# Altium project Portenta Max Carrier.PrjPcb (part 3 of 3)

## Sheet LORA.SchDoc: LORA
size A4; Author: Arturo Guadalupi; CompanyName: Arduino srl; DocumentNumber: ABX00043; Revision: V3.10; SheetNumber: 6; SheetTotal: 14; RevAuthor: S. Navaretti
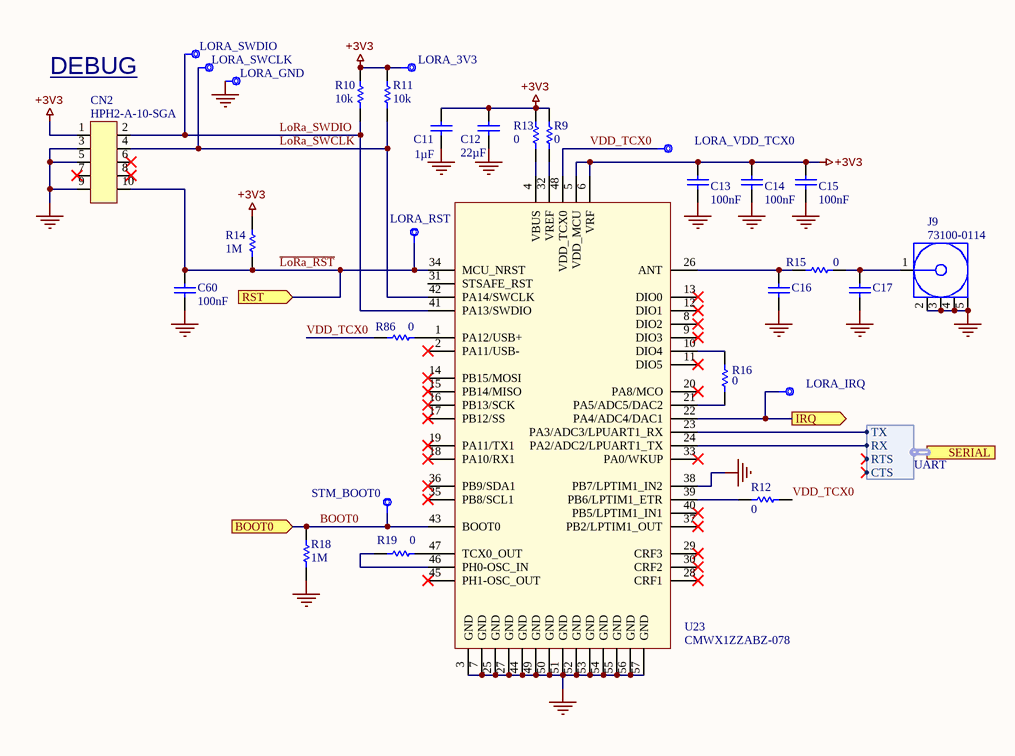
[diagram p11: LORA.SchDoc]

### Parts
C11  value 1µF  [CAP-0402]  (hidden comment: C0402C105K8PACTU)
C12  value 22µF  [CAP-0805]  (hidden comment: CL21A226MAQNNNE)
C13  value 100nF  [CAP-0402]  (hidden comment: C0402C104K4RACTU)
C14  value 100nF  [CAP-0402]  (hidden comment: C0402C104K4RACTU)
C15  value 100nF  [CAP-0402]  (hidden comment: C0402C104K4RACTU)
C16  C0402C104K4RACTU  [CAP-0402]  (value not drawn)
C17  C0402C104K4RACTU  [CAP-0402]  (value not drawn)
C60  value 100nF  [CAP-0402]  (hidden comment: C0402C104K4RACTU)
CN2  HPH2-A-10-SGA  [PINHEAD_2X05_127]
J9  73100-0114  [MOLX-731000114_V]
LORA_3V3  CMP-018-0005-A.3  [TP-1.00MM]  (value not drawn)  (no BOM)
LORA_GND  CMP-018-0005-A.3  [TP-1.00MM]  (value not drawn)  (no BOM)
LORA_IRQ  CMP-018-0005-A.3  [TP-1.00MM]  (value not drawn)  (no BOM)
LORA_RST  CMP-018-0005-A.3  [TP-1.00MM]  (value not drawn)  (no BOM)
LORA_SWCLK  CMP-018-0005-A.3  [TP-1.00MM]  (value not drawn)  (no BOM)
LORA_SWDIO  CMP-018-0005-A.3  [TP-1.00MM]  (value not drawn)  (no BOM)
LORA_VDD_TCX0  CMP-018-0005-A.3  [TP-1.00MM]  (value not drawn)  (no BOM)
R9  value 0  [RES-0402]  (hidden comment: CRCW04020000Z0EDC)
R10  value 10k  [RES-0402]  (hidden comment: CRCW040210K0FKED)
R11  value 10k  [RES-0402]  (hidden comment: CRCW040210K0FKED)
R12  value 0  [RES-0402]  (hidden comment: CRCW04020000Z0EDC)
R13  value 0  [RES-0402]  (hidden comment: CRCW04020000Z0EDC)
R14  value 1M  [RES-0402]  (hidden comment: CRCW04021M00FKED)
R15  value 0  [RES-0402]  (hidden comment: CRCW04020000Z0EDC)
R16  value 0  [RES-0402]  (hidden comment: CRCW04020000Z0EDC)
R18  value 1M  [RES-0402]  (hidden comment: CRCW04021M00FKED)
R19  value 0  [RES-0402]  (hidden comment: CRCW04020000Z0EDC)
R86  value 0  [RES-0402]  (hidden comment: CRCW04020000Z0EDC)
STM_BOOT0  CMP-018-0005-A.3  [TP-1.00MM]  (value not drawn)  (no BOM)
U23  CMWX1ZZABZ-078  [CMWX1ZZABZ]

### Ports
BOOT0 (in), IRQ (out), RST (in), SERIAL (harness UART)

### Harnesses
UART: CTS, RTS, RX, TX

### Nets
+3V3: C11.2 C12.2 C13.2 C14.2 C15.2 CN2.1 LORA_3V3.X R9.2 R10.2 R11.2 R13.2 R14.2 U23.5(VDD_MCU) U23.6(VRF)
GND: C11.1 C12.1 C13.1 C14.1 C15.1 C16.1 C17.1 C60.1 CN2.3 CN2.5 CN2.9 J9.2 J9.3 J9.4 J9.5 LORA_GND.X R18.2 U23.3(GND) U23.7(GND) U23.25(GND) U23.27(GND) U23.38(PB7/LPTIM1_IN2) U23.44(GND) U23.49(GND) U23.50(GND) U23.51(GND) U23.52(GND) U23.53(GND) U23.54(GND) U23.55(GND) U23.56(GND) U23.57(GND)
~{LoRa_RST}: C60.2 CN2.10 LORA_RST.X R14.1 U23.34(MCU_NRST) ; port RST  [project net GPIO.3]
BOOT0: R18.1 STM_BOOT0.X U23.43(BOOT0) ; port BOOT0  [project net LORA_BOOT0]
LORA_IRQ: LORA_IRQ.X U23.22(PA4/ADC4/DAC1) ; port IRQ
LoRa_SWCLK: CN2.4 LORA_SWCLK.X R11.1 U23.42(PA14/SWCLK)  [project net LoRa_SWCLK_6]
LoRa_SWDIO: CN2.2 LORA_SWDIO.X R10.1 U23.41(PA13/SWDIO)  [project net LoRa_SWDIO_6]
SERIAL3.RX: U23.24(PA2/ADC2/LPUART1_TX) ; port SERIAL.RX
SERIAL3.TX: U23.23(PA3/ADC3/LPUART1_RX) ; port SERIAL.TX
VDD_TCX0: LORA_VDD_TCX0.X R12.1 R86.2 U23.48(VDD_TCX0)  [project net VDD_TCX0_6]
NetC16_2: C16.2 R15.1 U23.26(ANT)
NetC17_2: C17.2 J9.1 R15.2
NetR9_1: R9.1 U23.32(VREF)
NetR12_2: R12.2 U23.39(PB6/LPTIM1_ETR)
NetR13_1: R13.1 U23.4(VBUS)
NetR16_1: R16.1 U23.10(DIO4)
NetR16_2: R16.2 U23.21(PA5/ADC5/DAC2)
NetR19_1: R19.1 U23.47(TCX0_OUT)
NetR19_2: R19.2 U23.46(PH0-OSC_IN)
NetR86_1: R86.1 U23.1(PA12/USB+)

Not connected (* = marked no-connect by the designer): CN2 6* 7* 8*; U23 2(PA11/USB-)* 8(DIO2)* 9(DIO3)* 11(DIO5)* 12(DIO1)* 13(DIO0)* 14(PB15/MOSI)* 15(PB14/MISO)* 16(PB13/SCK)* 17(PB12/SS)* 18(PA10/RX1)* 19(PA11/TX1)* 20(PA8/MCO)* 28(CRF1)* 29(CRF3)* 30(CRF2)* 31(STSAFE_RST) 33(PA0/WKUP)* 35(PB8/SCL1)* 36(PB9/SDA1)* 37(PB2/LPTIM1_OUT)* 40(PB5/LPTIM1_IN1)* 45(PH1-OSC_OUT)*

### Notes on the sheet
- DEBUG

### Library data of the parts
C11 = C0017-A.9: CAP CHIP 0402 1uF 10V X5R 10%; Manufacturer: KEMET; Code Arduino: 0133
C12 = C0111-A.2: CAP CHIP 0805 22uF 25V X5R 20%; Manufacturer: Samsung Electro-Mechanics; Code Arduino: C0111
C13-C17 C60 = C0012-A.9: CAP CHIP 0402 100nF 16V X7R 10%; Manufacturer: KEMET; Code Arduino: 0132
CN2 = J0068-A.5: CONN CONN STRIP THD 1,27 M/2/D 10v AuF H6,3 JTAG; Manufacturer: Adam Tech; Code Arduino: 0171
J9 = J0084-A.2: CONN PCB JACK RECEPTACLE SMA RA 50 OHM; Manufacturer: Molex; Impedance: 50R; Dielectric Material: PTFE; Body Plating: Gold; Connector Type: SMA,Socket; Frequency: 12Hz; Max Frequency: 18GHz; Code Arduino: J0084; Body Material: Brass; Voltage Rating: 500V
LORA_3V3 LORA_GND LORA_IRQ LORA_RST LORA_SWCLK LORA_SWDIO LORA_VDD_TCX0 STM_BOOT0 = UT0013-A.2: Test point 1.00mm
R9 R12 R13 R15 R16 R19 R86 = R0000-A.5: RES CHIP 0402 0R 1/16W; Manufacturer: Vishay; Power: 63mW; Tolerance: J; Code Arduino: 0039
R10 R11 = R0003-A.5: RES CHIP 0402 10K 1% 1/16W; Manufacturer: Vishay; Code Arduino: 0136; Power: 63mW
R14 R18 = R0058-A.5: RES CHIP 0402 1M 1% 1/16W; Manufacturer: Vishay; Code Arduino: 0139; Power: 63mW
U23 = M0000-A.4: MODULE LoRa; Manufacturer: Murata; Code Arduino: A5491

## Sheet DEBUGGER.SchDoc: DEBUGGER
size A3; Author: Arturo Guadalupi; CompanyName: Arduino srl; DocumentNumber: ABX00043; Revision: V3.10; SheetNumber: 3; SheetTotal: 14; RevAuthor: S. Navaretti
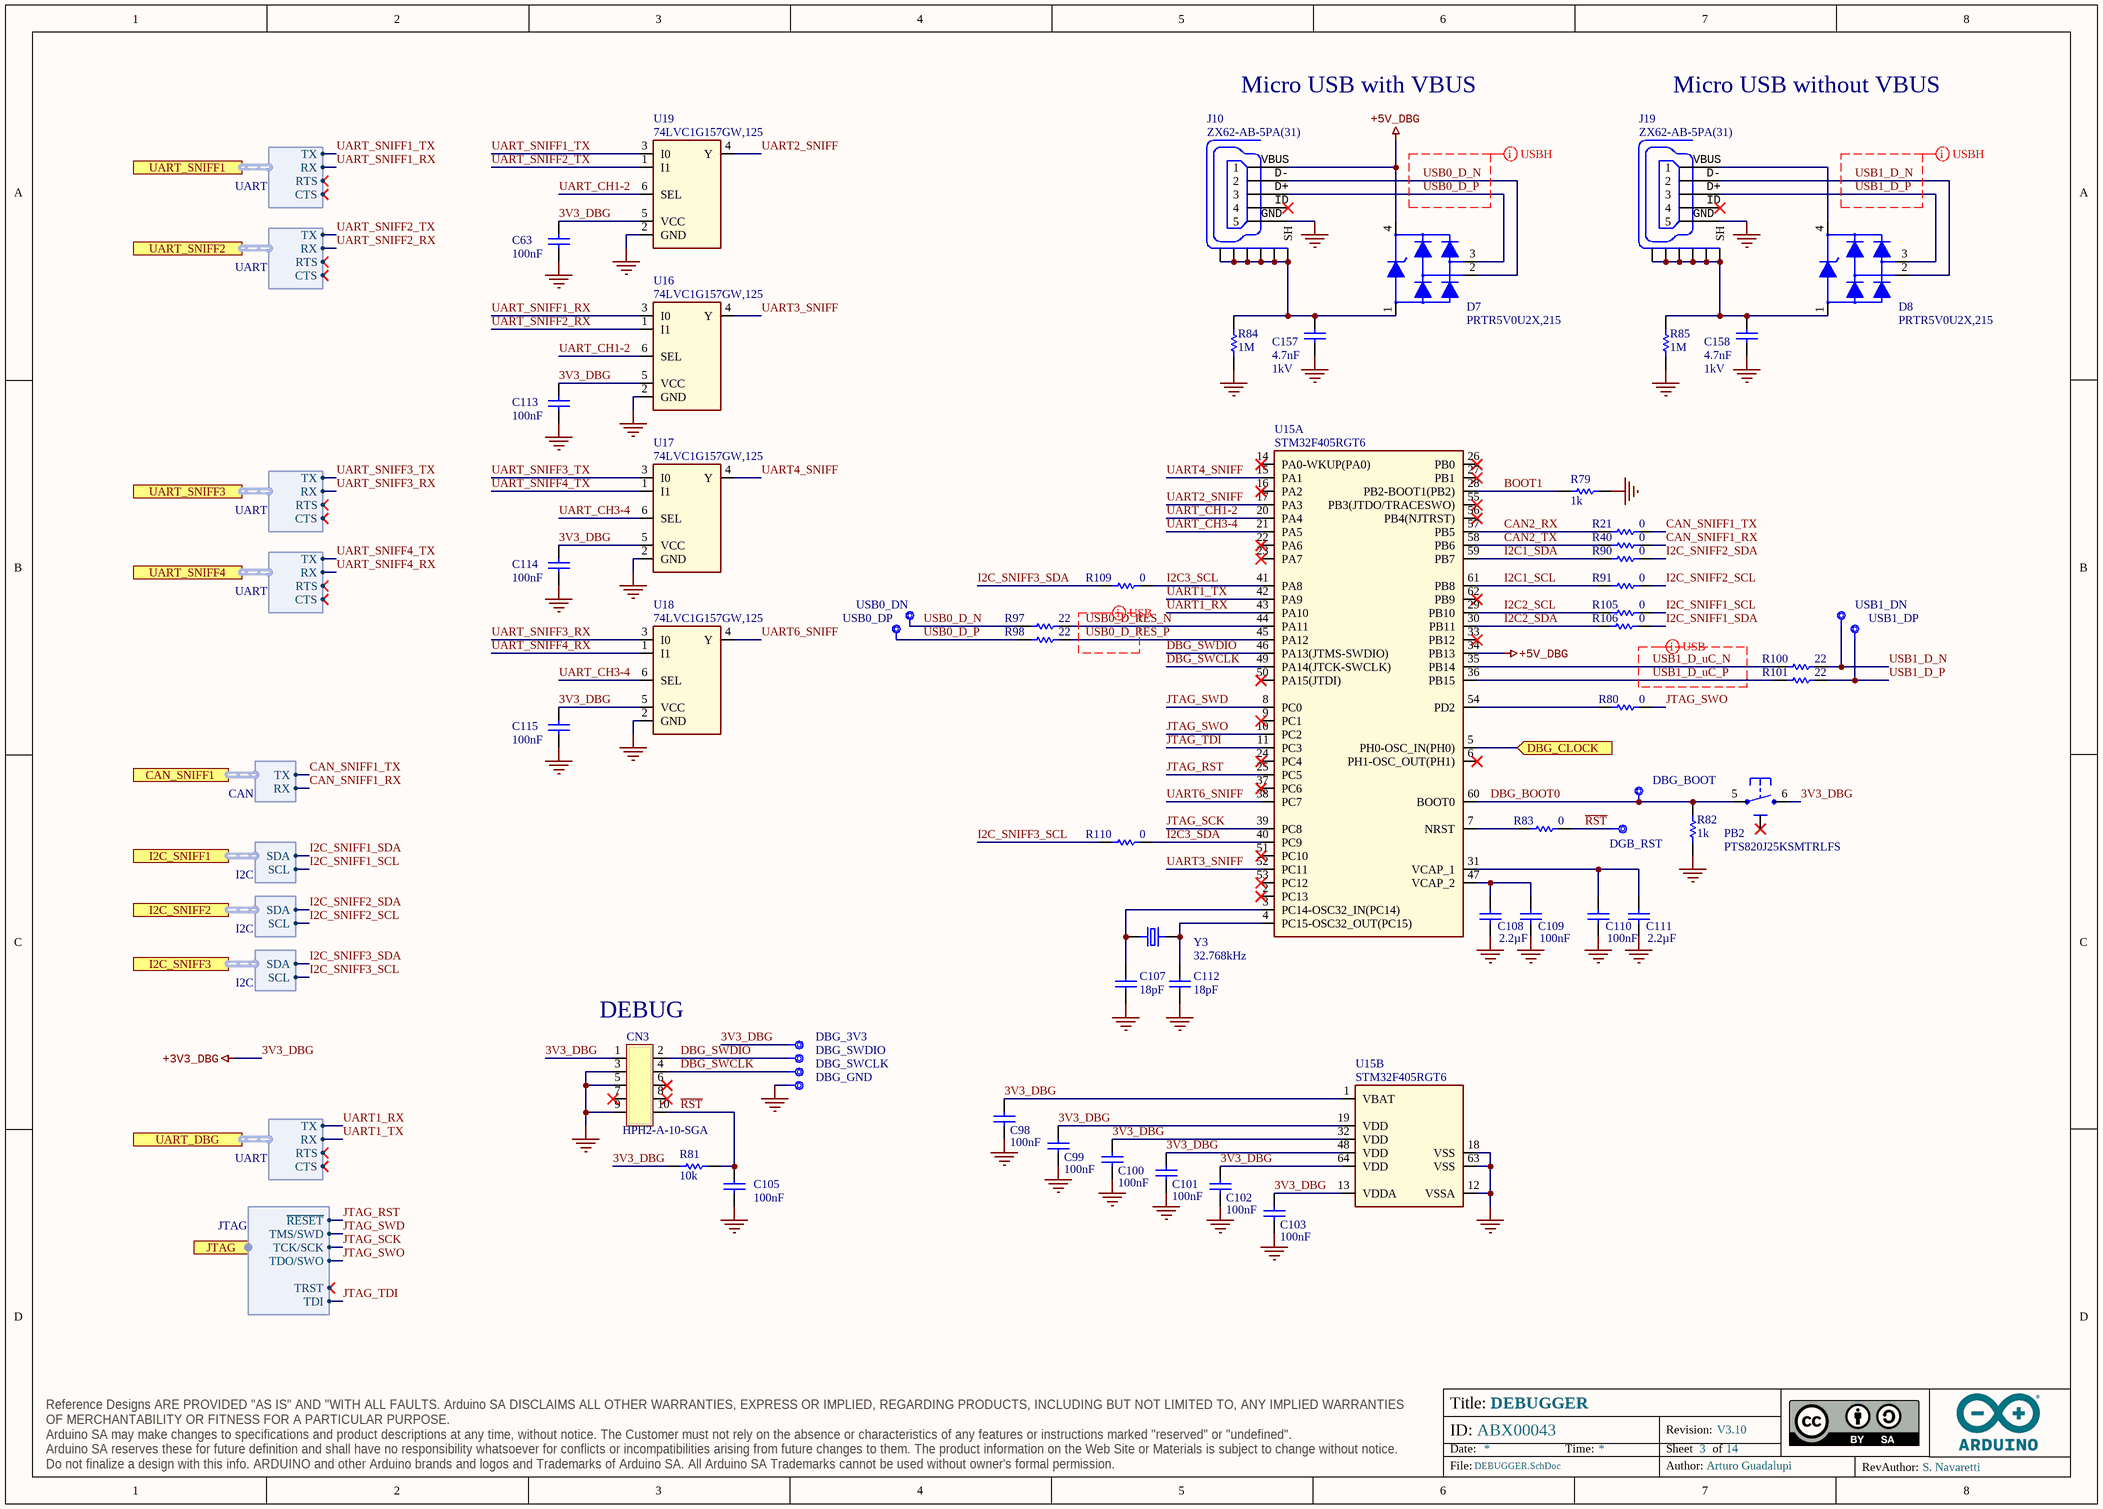
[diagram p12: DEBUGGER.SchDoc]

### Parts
C63  value 100nF  [CAP-0402]  (hidden comment: C0402C104K4RACTU)
C98  value 100nF  [CAP-0402]  (hidden comment: C0402C104K4RACTU)
C99  value 100nF  [CAP-0402]  (hidden comment: C0402C104K4RACTU)
C100  value 100nF  [CAP-0402]  (hidden comment: C0402C104K4RACTU)
C101  value 100nF  [CAP-0402]  (hidden comment: C0402C104K4RACTU)
C102  value 100nF  [CAP-0402]  (hidden comment: C0402C104K4RACTU)
C103  value 100nF  [CAP-0402]  (hidden comment: C0402C104K4RACTU)
C105  value 100nF  [CAP-0402]  (hidden comment: C0402C104K4RACTU)
C107  value 18pF  [CAP-0402]  (hidden comment: C0402C180J5GACTU)
C108  value 2.2µF  [CAP-0402]  (hidden comment: GRM155R60J225KE95D)
C109  value 100nF  [CAP-0402]  (hidden comment: C0402C104K4RACTU)
C110  value 100nF  [CAP-0402]  (hidden comment: C0402C104K4RACTU)
C111  value 2.2µF  [CAP-0402]  (hidden comment: GRM155R60J225KE95D)
C112  value 18pF  [CAP-0402]  (hidden comment: C0402C180J5GACTU)
C113  value 100nF  [CAP-0402]  (hidden comment: C0402C104K4RACTU)
C114  value 100nF  [CAP-0402]  (hidden comment: C0402C104K4RACTU)
C115  value 100nF  [CAP-0402]  (hidden comment: C0402C104K4RACTU)
C157  value 4.7nF  Voltage: 1kV  [CAP-0805]  (hidden comment: C0805C472KDRACTU)
C158  value 4.7nF  Voltage: 1kV  [CAP-0805]  (hidden comment: C0805C472KDRACTU)
CN3  HPH2-A-10-SGA  [PINHEAD_2X05_127]
D7  PRTR5V0U2X,215  [SOT190P230X110-4N]
D8  PRTR5V0U2X,215  [SOT190P230X110-4N]
DBG_3V3  CMP-018-0005-A.3  [TP-1.00MM]  (value not drawn)  (no BOM)
DBG_BOOT  CMP-018-0005-A.3  [TP-1.00MM]  (value not drawn)  (no BOM)
DBG_GND  CMP-018-0005-A.3  [TP-1.00MM]  (value not drawn)  (no BOM)
DBG_SWCLK  CMP-018-0005-A.3  [TP-1.00MM]  (value not drawn)  (no BOM)
DBG_SWDIO  CMP-018-0005-A.3  [TP-1.00MM]  (value not drawn)  (no BOM)
DGB_RST  CMP-018-0005-A.3  [TP-1.00MM]  (value not drawn)  (no BOM)
J10  ZX62-AB-5PA(31)  [ZX62-AB-5PA]
J19  ZX62-AB-5PA(31)  [ZX62-AB-5PA]
PB2  PTS820J25KSMTRLFS  [C&K_PTS820_NO_HOLES-1]
R21  value 0  [RES-0402]  (hidden comment: CRCW04020000Z0EDC)
R40  value 0  [RES-0402]  (hidden comment: CRCW04020000Z0EDC)
R79  value 1k  [RES-0402]  (hidden comment: CRCW04021K00FKEDC)
R80  value 0  [RES-0402]  (hidden comment: CRCW04020000Z0EDC)
R81  value 10k  [RES-0402]  (hidden comment: CRCW040210K0FKED)
R82  value 1k  [RES-0402]  (hidden comment: CRCW04021K00FKEDC)
R83  value 0  [RES-0402]  (hidden comment: CRCW04020000Z0EDC)
R84  value 1M  [RES-0402]  (hidden comment: CRCW04021M00FKED)
R85  value 1M  [RES-0402]  (hidden comment: CRCW04021M00FKED)
R90  value 0  [RES-0402]  (hidden comment: CRCW04020000Z0EDC)
R91  value 0  [RES-0402]  (hidden comment: CRCW04020000Z0EDC)
R97  value 22  [RES-0402]  (hidden comment: RC0402FR-0722RL)
R98  value 22  [RES-0402]  (hidden comment: RC0402FR-0722RL)
R100  value 22  [RES-0402]  (hidden comment: RC0402FR-0722RL)
R101  value 22  [RES-0402]  (hidden comment: RC0402FR-0722RL)
R105  value 0  [RES-0402]  (hidden comment: CRCW04020000Z0EDC)
R106  value 0  [RES-0402]  (hidden comment: CRCW04020000Z0EDC)
R109  value 0  [RES-0402]  (hidden comment: CRCW04020000Z0EDC)
R110  value 0  [RES-0402]  (hidden comment: CRCW04020000Z0EDC)
U15  STM32F405RGT6  [STM-LQFP64_M]  (parts A,B of 2)
U16  74LVC1G157GW,125  [TSOP95P280X110-6N]
U17  74LVC1G157GW,125  [TSOP95P280X110-6N]
U18  74LVC1G157GW,125  [TSOP95P280X110-6N]
U19  74LVC1G157GW,125  [TSOP95P280X110-6N]
USB0_DN  CMP-018-0005-A.3  [TP-1.00MM]  (value not drawn)  (no BOM)
USB0_DP  CMP-018-0005-A.3  [TP-1.00MM]  (value not drawn)  (no BOM)
USB1_DN  CMP-018-0005-A.3  [TP-1.00MM]  (value not drawn)  (no BOM)
USB1_DP  CMP-018-0005-A.3  [TP-1.00MM]  (value not drawn)  (no BOM)
Y3  Frequency: 32.768kHz  [ABS07]  (hidden comment: CM315D32768DZFT)

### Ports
CAN_SNIFF1 (harness CAN), DBG_CLOCK (in), I2C_SNIFF1 (harness I2C), I2C_SNIFF2 (harness I2C), I2C_SNIFF3 (harness I2C), JTAG (harness JTAG), UART_DBG (harness UART), UART_SNIFF1 (harness UART), UART_SNIFF2 (harness UART), UART_SNIFF3 (harness UART), UART_SNIFF4 (harness UART)

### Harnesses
UART: RX, TX, RTS, CTS
I2C: SCL, SDA
CAN: RX, TX
JTAG: ~{RESET}, TCK/SCK, TDI, TDO/SWO, TMS/SWD, TRST

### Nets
+3V3_DBG: C63.1 C98.2 C99.2 C100.2 C101.2 C102.2 C103.2 C113.1 C114.1 C115.1 CN3.1 DBG_3V3.X PB2.6 R81.2 U15.1(VBAT) U15.13(VDDA) U15.19(VDD) U15.32(VDD) U15.48(VDD) U15.64(VDD) U16.5(VCC) U17.5(VCC) U18.5(VCC) U19.5(VCC)  [also labelled 3V3_DBG]
+5V_DBG: D7.4 J10.1 U15.34(PB13)
GND: C63.2 C98.1 C99.1 C100.1 C101.1 C102.1 C103.1 C105.1 C107.2 C108.1 C109.1 C110.1 C111.1 C112.2 C113.2 C114.2 C115.2 C157.1 C158.1 CN3.3 CN3.5 CN3.9 DBG_GND.X J10.5 J19.5 R79.1 R82.1 R84.1 R85.1 U15.12(VSSA) U15.18(VSS) U15.63(VSS) U16.2(GND) U17.2(GND) U18.2(GND) U19.2(GND)
~{RST}: C105.2 CN3.10 DGB_RST.X R81.1 R83.2  [project net ~{RST}_3]
BOOT1: R79.2 U15.28(PB2-BOOT1(PB2))  [project net BOOT1_3]
CAN2_RX: R21.1 U15.57(PB5)  [project net CAN2_RX_3]
CAN2_TX: R40.1 U15.58(PB6)  [project net CAN2_TX_3]
CAN_SNIFF1_RX: R40.2 ; port CAN_SNIFF1.RX  [project net CAN1.RX]
CAN_SNIFF1_TX: R21.2 ; port CAN_SNIFF1.TX  [project net CAN1.TX]
DBG_BOOT0: DBG_BOOT.X PB2.5 R82.2 U15.60(BOOT0)  [project net DBG_BOOT0_3]
DBG_SWCLK: CN3.4 DBG_SWCLK.X U15.49(PA14(JTCK-SWCLK))  [project net DBG_SWCLK_3]
DBG_SWDIO: CN3.2 DBG_SWDIO.X U15.46(PA13(JTMS-SWDIO))  [project net DBG_SWDIO_3]
I2C1_SCL: R91.1 U15.61(PB8)  [project net I2C1_SCL_3]
I2C1_SDA: R90.1 U15.59(PB7)  [project net I2C1_SDA_3]
I2C2_SCL: R105.1 U15.29(PB10)  [project net I2C2_SCL_3]
I2C2_SDA: R106.1 U15.30(PB11)  [project net I2C2_SDA_3]
I2C3_SCL: R109.2 U15.41(PA8)  [project net I2C3_SCL_3]
I2C3_SDA: R110.2 U15.40(PC9)  [project net I2C3_SDA_3]
I2C_SNIFF1_SCL: R105.2 ; port I2C_SNIFF1.SCL  [project net I2C0.SCL]
I2C_SNIFF1_SDA: R106.2 ; port I2C_SNIFF1.SDA  [project net I2C0.SDA]
I2C_SNIFF2_SCL: R91.2 ; port I2C_SNIFF2.SCL  [project net I2C1.SCL]
I2C_SNIFF2_SDA: R90.2 ; port I2C_SNIFF2.SDA  [project net I2C1.SDA]
I2C_SNIFF3_SCL: R110.1 ; port I2C_SNIFF3.SCL  [project net I2C2.SCL]
I2C_SNIFF3_SDA: R109.1 ; port I2C_SNIFF3.SDA  [project net I2C2.SDA]
JTAG_RST: U15.25(PC5) ; port JTAG.~{RESET}  [project net JTAG.~{RESET}]
JTAG_SCK: U15.39(PC8) ; port JTAG.TCK/SCK  [project net JTAG.TCK/SCK]
JTAG_SWD: U15.8(PC0) ; port JTAG.TMS/SWD  [project net JTAG.TMS/SWD]
JTAG_SWO: R80.2 U15.10(PC2) ; port JTAG.TDO/SWO  [project net JTAG.TDO/SWO]
JTAG_TDI: U15.11(PC3) ; port JTAG.TDI  [project net JTAG.TDI]
UART1_RX: U15.43(PA10) ; port UART_DBG.TX  [project net SERIAL2.TX]
UART1_TX: U15.42(PA9) ; port UART_DBG.RX  [project net SERIAL2.RX]
UART2_SNIFF: U15.17(PA3) U19.4(Y)  [project net UART2_SNIFF_3]
UART3_SNIFF: U15.52(PC11) U16.4(Y)  [project net UART3_SNIFF_3]
UART4_SNIFF: U15.15(PA1) U17.4(Y)  [project net UART4_SNIFF_3]
UART6_SNIFF: U15.38(PC7) U18.4(Y)  [project net UART6_SNIFF_3]
UART_CH1-2: U15.20(PA4) U16.6(SEL) U19.6(SEL)  [project net UART_CH1-2_3]
UART_CH3-4: U15.21(PA5) U17.6(SEL) U18.6(SEL)  [project net UART_CH3-4_3]
UART_SNIFF1_RX: U16.3(I0) ; port UART_SNIFF1.RX  [project net SERIAL0.RX]
UART_SNIFF1_TX: U19.3(I0) ; port UART_SNIFF1.TX  [project net SERIAL0.TX]
UART_SNIFF2_RX: U16.1(I1) ; port UART_SNIFF2.RX  [project net SERIAL1.RX]
UART_SNIFF2_TX: U19.1(I1) ; port UART_SNIFF2.TX  [project net SERIAL1.TX]
UART_SNIFF3_RX: U18.3(I0) ; port UART_SNIFF3.RX  [project net SERIAL3.RX]
UART_SNIFF3_TX: U17.3(I0) ; port UART_SNIFF3.TX  [project net SERIAL3.TX]
UART_SNIFF4_RX: U18.1(I1) ; port UART_SNIFF4.RX
UART_SNIFF4_TX: U17.1(I1) ; port UART_SNIFF4.TX
USB0_D_N: D7.2 J10.2 R97.1 USB0_DN.X  [project net USB0_D_N_3]
USB0_D_P: D7.3 J10.3 R98.1 USB0_DP.X  [project net USB0_D_P_3]
USB0_D_RES_N: R97.2 U15.44(PA11)  [project net USB0_D_RES_N_3]
USB0_D_RES_P: R98.2 U15.45(PA12)  [project net USB0_D_RES_P_3]
USB1_D_N: D8.2 J19.2 R100.2 USB1_DN.X  [project net USB1_D_N_3]
USB1_D_P: D8.3 J19.3 R101.2 USB1_DP.X  [project net USB1_D_P_3]
USB1_D_uC_N: R100.1 U15.35(PB14)  [project net USB1_D_uC_N_3]
USB1_D_uC_P: R101.1 U15.36(PB15)  [project net USB1_D_uC_P_3]
Net12MHz_CLK_X: U15.5(PH0-OSC_IN(PH0)) ; port DBG_CLOCK
NetC107_1: C107.1 U15.3(PC14-OSC32_IN(PC14)) Y3.2
NetC108_2: C108.2 C109.2 U15.47(VCAP_2)
NetC110_2: C110.2 C111.2 U15.31(VCAP_1)
NetC112_1: C112.1 U15.4(PC15-OSC32_OUT(PC15)) Y3.1
NetC157_2: C157.2 D7.1 J10.M1(SH) J10.M2(SH) J10.M3(SH) J10.M4(SH) J10.M5(SH) J10.M6(SH) R84.2
NetC158_2: C158.2 D8.1 J19.M1(SH) J19.M2(SH) J19.M3(SH) J19.M4(SH) J19.M5(SH) J19.M6(SH) R85.2
NetD8_4: D8.4 J19.1
NetR80_1: R80.1 U15.54(PD2)
NetR83_1: R83.1 U15.7(NRST)

Not connected (* = marked no-connect by the designer): CN3 6* 7* 8*; J10 4*; J19 4*; PB2 PAD*; U15 2(PC13)* 6(PH1-OSC_OUT(PH1))* 9(PC1)* 14(PA0-WKUP(PA0))* 16(PA2)* 22(PA6)* 23(PA7)* 24(PC4)* 26(PB0)* 27(PB1)* 33(PB12)* 37(PC6)* 50(PA15(JTDI))* 51(PC10)* 53(PC12)* 55(PB3(JTDO/TRACESWO))* 56(PB4(NJTRST))* 62(PB9)*

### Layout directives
differential pair; differential pair class USB: USB0_D_N, USB0_D_P, USB0_D_RES_N, USB0_D_RES_P, USB1_D_N, USB1_D_P, USB1_D_uC_N, USB1_D_uC_P

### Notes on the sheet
- Micro USB with VBUS
- Micro USB without VBUS
- (near CN3) DEBUG

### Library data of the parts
C63 C98-C103 C105 C109 C110 C113-C115 = C0012-A.9: as C13-C17 on sheet LORA
C107 C112 = C0026-A.11: CAP CHIP 0402 18pF C0G 50V 5%; Manufacturer: KEMET; Code Arduino: 2320
C108 C111 = C0031-A.9: CAP CHIP 0402 2.2uF 6.3V X5R 10%; Manufacturer: Murata; Code Arduino: A5529
C157 C158 = C0059-A.9: CAP CHIP 0805 4.7nF 1000V X7R 10%; Manufacturer: KEMET; Code Arduino: 0689
CN3 = J0068-A.5: as CN2 on sheet LORA
D7 D8 = D0025-A.3: TVS ARRAY 4LIN.8kV 1pF SOT143B; Manufacturer: Nexperia; Device Type: ESD protection; Code Arduino: 2209
DBG_3V3 DBG_BOOT DBG_GND DBG_SWCLK DBG_SWDIO DGB_RST USB0_DN USB0_DP USB1_DN USB1_DP = UT0013-A.2: Test point 1.00mm
J10 J19 = J0039-A.3: CONN USB MICRO F/90^ SMD TipoAB 5x1; Manufacturer: Hirose; Code Arduino: 2219
PB2 = B0006-A.6: PUSHBUTTON SMD PTS820 NO HOLES; Manufacturer: C&K; Mechanical Life: 100000Cycles; Code Arduino: A5506; Actuator Type: Standard
R21 R40 R80 R83 R90 R91 R105 R106 R109 R110 = R0000-A.5: RES CHIP 0402 0R 1/16W; Manufacturer: Vishay; Code Arduino: 0039; Power: 63mW; Tolerance: J
R79 R82 = R0007-A.5: RES CHIP 0402 1K 1% 1/16W; Manufacturer: Vishay; Code Arduino: 0140; Power: 63mW
R81 = R0003-A.5: as R10 on sheet LORA
R84 R85 = R0058-A.5: as R14 on sheet LORA
R97 R98 R100 R101 = R0009-A.5: RES CHIP 0402 22R 1% 1/16W; Manufacturer: Yageo; Power: 63mW; Code Arduino: 0468
U15 = U0118-A.4: MCU 32-bit STM32F ARM Cortex M4F RISC 1024KB Flash 2.5V/3.3V 64-Pin LQFP Tray; Manufacturer: ST Microelectronics; Interface: I2C,SPI,USB,CAN,IrDA,UART,USART,LIN,I2S; Min Supply Voltage: 1.8V; Number of Timers/Counters: 14; Data Bus Width: 32b; Number of SPI Channels: 3; Number of Programmable I/O: 51; Watchdog Timer: Yes; Oscillator Type: Internal; Number of ADC Channels: 16; Peripherals: Brown-out Detect/Reset,POR,PWM,WDT,DMA,LCD,I2C; RAM Size: 196KB; Number of UART Channels: 2; Max Frequency: 168MHz; Code Arduino: U0118; Max Supply Voltage: 3.6V
U16-U19 = U0119-A.4: IC SINGLE 2-INPUT MUX 6TSSOP; Manufacturer: Nexperia; Max Supply Voltage: 5.5V; Min Supply Voltage: 1.65V; Code Arduino: U0119
Y3 = X0003-A.4: CRYSTAL 32.768kHz 20ppm 12.5pF SMD 1.6x0.9mm; Manufacturer: Citizen FineDevice; Code Arduino: 0213; Series Resistance: 70kR; Frequency Stability: 0.12%

## Sheet ETH_CONNECTOR.SchDoc: ETHERNET
size A4; Author: Arturo Guadalupi; CompanyName: Arduino srl; DocumentNumber: ABX00043; Revision: V3.10; SheetNumber: 14; SheetTotal: 14; RevAuthor: S. Navaretti
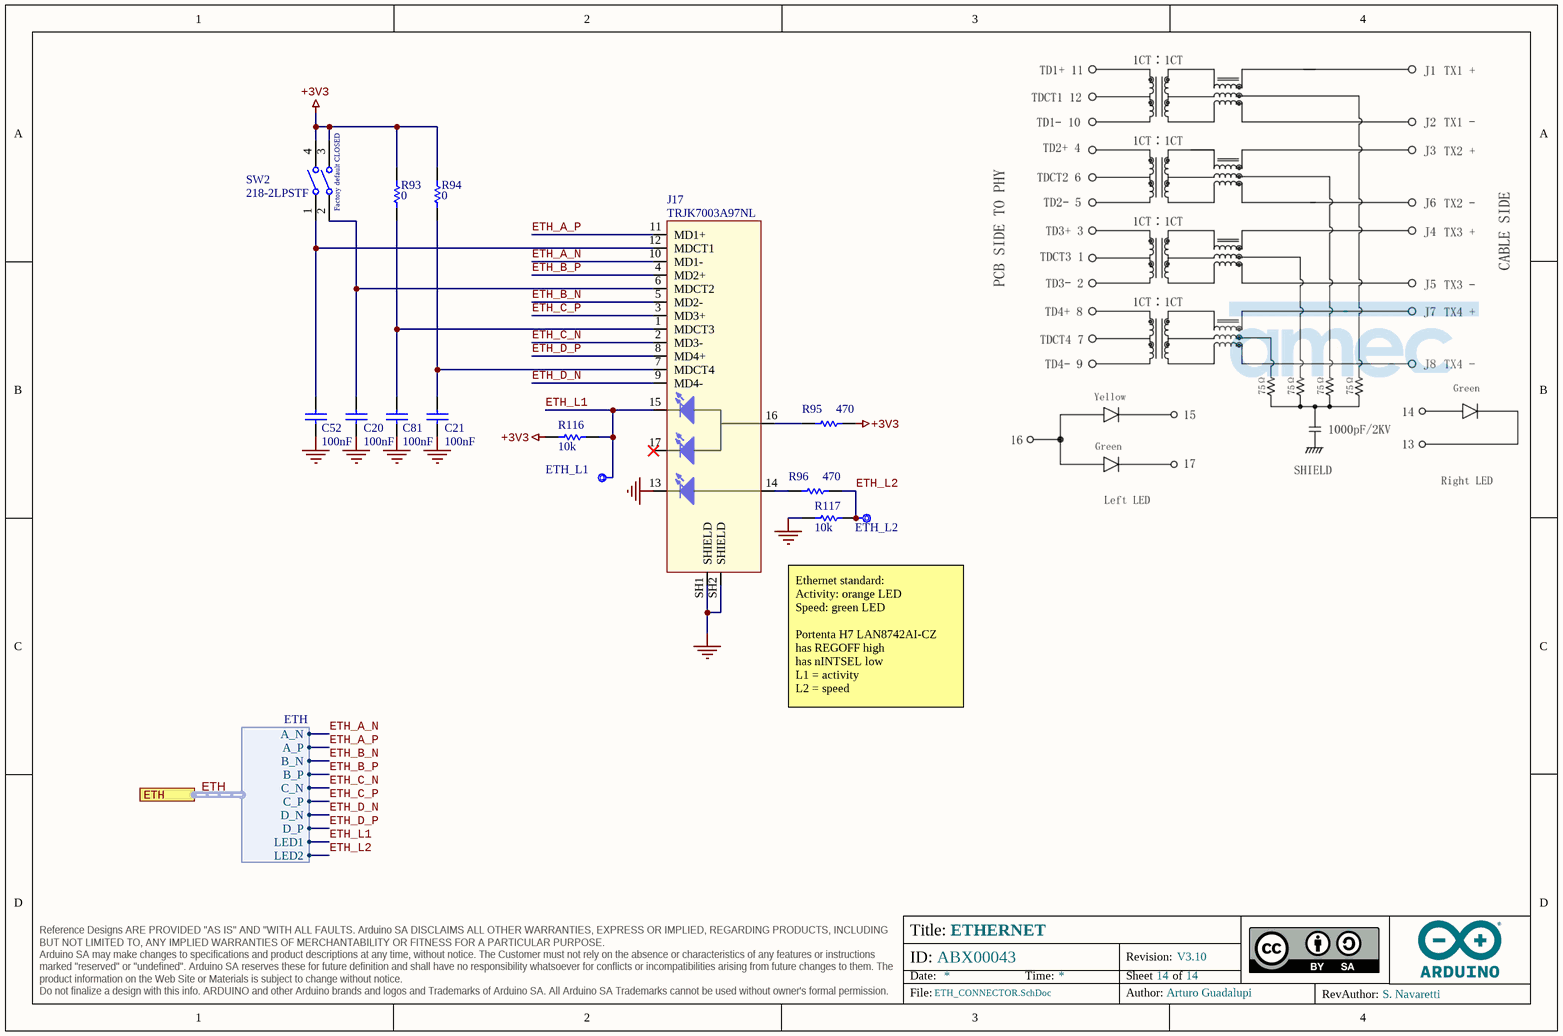
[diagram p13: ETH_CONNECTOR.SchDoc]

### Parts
C20  value 100nF  [CAP-0402]  (hidden comment: C0402C104K4RACTU)
C21  value 100nF  [CAP-0402]  (hidden comment: C0402C104K4RACTU)
C52  value 100nF  [CAP-0402]  (hidden comment: C0402C104K4RACTU)
C81  value 100nF  [CAP-0402]  (hidden comment: C0402C104K4RACTU)
ETH_L1  CMP-018-0005-A.3  [TP-1.00MM]  (value not drawn)  (no BOM)
ETH_L2  CMP-018-0005-A.3  [TP-1.00MM]  (value not drawn)  (no BOM)
J17  TRJK7003A97NL  [TRJK0071AWNL -Footprint-2]
R93  value 0  [RES-0402]  (hidden comment: CRCW04020000Z0EDC)
R94  value 0  [RES-0402]  (hidden comment: CRCW04020000Z0EDC)
R95  value 470  [RES-0402]  (hidden comment: CRCW0402470RJNED)
R96  value 470  [RES-0402]  (hidden comment: CRCW0402470RJNED)
R116  value 10k  [RES-0402]  (hidden comment: CRCW040210K0FKED)
R117  value 10k  [RES-0402]  (hidden comment: CRCW040210K0FKED)
SW2  218-2LPSTF  [CTS-218-2LPST_V]

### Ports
ETH (harness ETH)

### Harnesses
ETH: A_N, A_P, B_N, B_P, C_N, C_P, D_N, D_P, LED1, LED2

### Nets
+3V3: R93.2 R94.2 R95.2 R116.2 SW2.3 SW2.4
GND: C20.2 C21.2 C52.2 C81.2 J17.13 J17.SH1(SHIELD) J17.SH2(SHIELD) R117.2
ETH_A_N: J17.10(MD1-) ; port ETH.A_N  [project net ETH.A_N]
ETH_A_P: J17.11(MD1+) ; port ETH.A_P  [project net ETH.A_P]
ETH_B_N: J17.5(MD2-) ; port ETH.B_N  [project net ETH.B_N]
ETH_B_P: J17.4(MD2+) ; port ETH.B_P  [project net ETH.B_P]
ETH_C_N: J17.2(MD3-) ; port ETH.C_N  [project net ETH.C_N]
ETH_C_P: J17.3(MD3+) ; port ETH.C_P  [project net ETH.C_P]
ETH_D_N: J17.9(MD4-) ; port ETH.D_N  [project net ETH.D_N]
ETH_D_P: J17.8(MD4+) ; port ETH.D_P  [project net ETH.D_P]
ETH_L1: ETH_L1.X J17.15 R116.1 ; port ETH.LED1  [project net ETH.LED1]
ETH_L2: ETH_L2.X R96.2 R117.1 ; port ETH.LED2  [project net ETH.LED2]
NetC20_1: C20.1 J17.6(MDCT2) SW2.2
NetC21_1: C21.1 J17.7(MDCT4) R94.1
NetC52_1: C52.1 J17.12(MDCT1) SW2.1
NetC81_1: C81.1 J17.1(MDCT3) R93.1
NetJ17_14: J17.14 R96.1
NetJ17_16: J17.16 R95.1

Not connected (* = marked no-connect by the designer): J17 17*

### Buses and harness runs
harness ETH = port ETH

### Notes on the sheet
- (near J17) Ethernet standard:
  Activity: orange LED
  Speed: green LED
  Portenta H7 LAN8742AI-CZ
  has REGOFF high
  has nINTSEL low
  L1 = activity
  L2 = speed

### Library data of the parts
C20 C21 C52 C81 = C0012-A.9: as C13-C17 on sheet LORA
ETH_L1 ETH_L2 = UT0013-A.2: Test point 1.00mm
J17 = J0027-A.4: CONN ETHERNET 1GIGABIT; Manufacturer: TRXCOM; Code Arduino: A5565
R93 R94 = R0000-A.5: as R21 on sheet DEBUGGER
R95 R96 = R0055-A.6: RES CHIP 0402 470R 5% 1/16W; Manufacturer: Vishay; Power: 63mW; Code Arduino: R0055; Tolerance: 1%
R116 R117 = R0003-A.5: as R10 on sheet LORA
SW2 = S0016-A.2: DIP SWITCH SPST LATCHED SMD 0.025A, 24VDC, NORMALLY ON; Manufacturer: CTS Corporation; Part Number: 218-2LPSTR; Number of Positions: 2; Actuator Type: Slide (Standard); Washable: Yes; Pitch: 0.05inch; Electrical Life: 1000Cycles; Current Rating: 25mA; Code Arduino: S0016; Voltage Rating (DC): 24V; Contact Resistance: 100mR

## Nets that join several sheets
+1V8: POWER (1V8.X C87.2 U12.5), AUDIO (9 pins)
+3V3: TOP (8 pins), POWER (8 pins), FIELDBUS (10 pins), HDConn_FEMALE (6 pins), AUDIO (9 pins), SD_CONNECTOR (J11.4), CELL_MODEM (10 pins), USB_HUB (8 pins), CAMERA_CONNECTOR (C18.2 J4.20), LORA (14 pins), ETH_CONNECTOR (6 pins)
+3V3_DBG: TOP (D11.1), POWER (5 pins), DEBUGGER (24 pins)
+3V3_PCIE: POWER (9 pins), MINI_PCIE (9 pins)
+3V8: TOP (J5.31), POWER (9 pins), CELL_MODEM (12 pins)
+5V: TOP (J5.36 R92.1), POWER (15 pins), FIELDBUS (C58.1 F1.2 U5.3), USB_HUB (R41.2 R42.2 R56.1 R112.2), USBA_CONNECTORS (C94.2 C95.2 U7.2 U7.3)
+5V_DBG: POWER (5V_DBG.X C97.1 U14.1 U14.3), DEBUGGER (D7.4 J10.1 U15.34)
GND: TOP (12 pins), POWER (70 pins), FIELDBUS (16 pins), HDConn_FEMALE (12 pins), AUDIO (33 pins), MINI_PCIE (36 pins), SD_CONNECTOR (6 pins), CELL_MODEM (101 pins), USB_HUB (22 pins), USBA_CONNECTORS (11 pins), CAMERA_CONNECTOR (5 pins), LORA (32 pins), DEBUGGER (36 pins), ETH_CONNECTOR (8 pins)
485/232n: FIELDBUS (485/232n.X R78.2 U4.14), HDConn_FEMALE (J2.61)
A0: TOP (J5.5), HDConn_FEMALE (J2.73)
A1: TOP (J5.6), HDConn_FEMALE (J2.75), MINI_PCIE (J8.20)
A2: TOP (J5.7), HDConn_FEMALE (J2.77)
A3: TOP (J5.8), HDConn_FEMALE (J2.79)
A4: TOP (J5.9), HDConn_FEMALE (J2.74)
A5: TOP (J5.10), HDConn_FEMALE (J2.76)
A6: TOP (J5.11), HDConn_FEMALE (J2.78)
A7: TOP (J5.12), HDConn_FEMALE (J2.80)
ANALOG.VREF_N: TOP (J5.4), HDConn_FEMALE (J2.72)
ANALOG.VREF_P: TOP (J5.3), HDConn_FEMALE (J2.71)
AUDIO_MCLK_EN: TOP (MCLK_EN.X R61.1 R62.2), HDConn_FEMALE (J2.46)
AUDIO_RST: HDConn_FEMALE (J2.48), AUDIO (AUDIO_RST.X U2.32)
BOOT: TOP (SW1.1), HDConn_FEMALE (J2.1)
BT_SEL: TOP (SW1.2), HDConn_FEMALE (J2.3)
CAMERA.CK_N: HDConn_FEMALE (J2.20), CAMERA_CONNECTOR (J4.13)
CAMERA.CK_P: HDConn_FEMALE (J2.18), CAMERA_CONNECTOR (J4.14)
CAMERA.D0_N: HDConn_FEMALE (J2.16), CAMERA_CONNECTOR (J4.7)
CAMERA.D0_P: HDConn_FEMALE (J2.14), CAMERA_CONNECTOR (J4.8)
CAMERA.D1_N: HDConn_FEMALE (J2.12), CAMERA_CONNECTOR (J4.10)
CAMERA.D1_P: HDConn_FEMALE (J2.10), CAMERA_CONNECTOR (J4.11)
CAMERA.D2_N: HDConn_FEMALE (J2.8), CAMERA_CONNECTOR (J4.4)
CAMERA.D2_P: HDConn_FEMALE (J2.6), CAMERA_CONNECTOR (J4.5)
CAMERA.D3_N: HDConn_FEMALE (J2.4), CAMERA_CONNECTOR (J4.1)
CAMERA.D3_P: HDConn_FEMALE (J2.2), CAMERA_CONNECTOR (J4.2)
CAMERA.HS: HDConn_FEMALE (J2.22), CAMERA_CONNECTOR (J4.3)
CAN0.RX: TOP (CAN0_RX.X J5.40), HDConn_FEMALE (J1.52)
CAN0.TX: TOP (CAN0_TX.X J5.38), HDConn_FEMALE (J1.50)
CAN1.RX: TOP (CAN1_RX.X), FIELDBUS (U5.4), HDConn_FEMALE (J1.51), DEBUGGER (R40.2)
CAN1.TX: TOP (CAN1_TX.X), FIELDBUS (U5.1), HDConn_FEMALE (J1.49), DEBUGGER (R21.2)
CELL_PON: HDConn_FEMALE (J2.54), CELL_MODEM (PWR_ON.X Q7.4 R17.2)
CELL_RST: HDConn_FEMALE (J2.50), CELL_MODEM (Q7.1 R3.2 RST.X)
~{EN_CAN}: FIELDBUS (EN_CAN.X R49.1 U5.8), HDConn_FEMALE (J2.65)
EN_485: FIELDBUS (EN_485.X R47.1 U4.10), HDConn_FEMALE (J2.63)
ETH.A_N: HDConn_FEMALE (J1.3), ETH_CONNECTOR (J17.10)
ETH.A_P: HDConn_FEMALE (J1.1), ETH_CONNECTOR (J17.11)
ETH.B_N: HDConn_FEMALE (J1.7), ETH_CONNECTOR (J17.5)
ETH.B_P: HDConn_FEMALE (J1.5), ETH_CONNECTOR (J17.4)
ETH.C_N: HDConn_FEMALE (J1.11), ETH_CONNECTOR (J17.2)
ETH.C_P: HDConn_FEMALE (J1.9), ETH_CONNECTOR (J17.3)
ETH.D_N: HDConn_FEMALE (J1.15), ETH_CONNECTOR (J17.9)
ETH.D_P: HDConn_FEMALE (J1.13), ETH_CONNECTOR (J17.8)
ETH.LED1: HDConn_FEMALE (J1.17), ETH_CONNECTOR (ETH_L1.X J17.15 R116.1)
ETH.LED2: HDConn_FEMALE (J1.19), ETH_CONNECTOR (ETH_L2.X R96.2 R117.1)
FD_TX_TERM: FIELDBUS (R46.1 U4.12), HDConn_FEMALE (J2.56)
GPIO.3: HDConn_FEMALE (J2.52), LORA (5 pins)
GPIO.6: POWER (INT_BQ.X R76.2 U11.7), HDConn_FEMALE (J2.58)
H/Fn: FIELDBUS (H/Fn.X R118.2 U4.15), HDConn_FEMALE (J2.59)
I2C0.SCL: TOP (HUB_SCL.X), POWER (U11.5), HDConn_FEMALE (J1.46), AUDIO (R34.2 U2.2), MINI_PCIE (J8.30), USB_HUB (U3.24), CAMERA_CONNECTOR (J4.18), DEBUGGER (R105.2)
I2C0.SDA: TOP (HUB_SDA.X), POWER (U11.6), HDConn_FEMALE (J1.44), AUDIO (R35.2 U2.1), MINI_PCIE (J8.32), USB_HUB (U3.22), CAMERA_CONNECTOR (J4.19), DEBUGGER (R106.2)
I2C1.SCL: TOP (I2C1_SCL.X J5.29), HDConn_FEMALE (J1.45), DEBUGGER (R91.2)
I2C1.SDA: TOP (I2C1_SDA.X J5.27), HDConn_FEMALE (J1.43), DEBUGGER (R90.2)
I2C2.SCL: TOP (I2C2_SCL.X J5.34), HDConn_FEMALE (J2.47), DEBUGGER (R110.1)
I2C2.SDA: TOP (I2C2_SDA.X J5.32), HDConn_FEMALE (J2.45), DEBUGGER (R109.1)
I2S.CK: TOP (I2S_CK.X), HDConn_FEMALE (J1.56), AUDIO (U2.38)
I2S.SDI: TOP (I2S_SDI.X), HDConn_FEMALE (J1.60), AUDIO (U2.36)
I2S.SDO: TOP (I2S_SDO.X), HDConn_FEMALE (J1.62), AUDIO (U2.39)
I2S.WS: TOP (I2S_WS.X), HDConn_FEMALE (J1.58), AUDIO (U2.40)
JTAG.~{RESET}: TOP (JTAG_RST.X), HDConn_FEMALE (CN1.10 J1.73), DEBUGGER (U15.25)
JTAG.TCK/SCK: TOP (JTAG_SCK.X), HDConn_FEMALE (CN1.4 J1.77), DEBUGGER (U15.39)
JTAG.TDI: TOP (JTAG_TDI.X), HDConn_FEMALE (CN1.8 J1.78), DEBUGGER (U15.11)
JTAG.TDO/SWO: TOP (JTAG_SWO.X), HDConn_FEMALE (CN1.6 J1.79), DEBUGGER (R80.2 U15.10)
JTAG.TMS/SWD: TOP (JTAG_SWD.X), HDConn_FEMALE (CN1.2 J1.75), DEBUGGER (U15.8)
LORA_BOOT0: HDConn_FEMALE (J2.67), LORA (R18.1 STM_BOOT0.X U23.43)
LORA_IRQ: HDConn_FEMALE (J2.60), LORA (LORA_IRQ.X U23.22)
Net12MHz_CLK_X: TOP (12MHz_CLK.X R60.1 U9.3 U10.2), DEBUGGER (U15.5)
NetAUDIO_MCLK_X: TOP (AUDIO_MCLK.X R60.2 R61.2 U10.4), AUDIO (U2.37)
NetJ2_5: TOP (PB1.6), HDConn_FEMALE (J2.5)
PCIe.CK_N: HDConn_FEMALE (J2.19), MINI_PCIE (J8.11)
PCIe.CK_P: HDConn_FEMALE (J2.17), MINI_PCIE (J8.13)
PCIe.RST: HDConn_FEMALE (J2.21), MINI_PCIE (J8.22)
PCIe.RX_N: HDConn_FEMALE (J2.15), MINI_PCIE (J8.23)
PCIe.RX_P: HDConn_FEMALE (J2.13), MINI_PCIE (J8.25)
PCIe.TX_N: HDConn_FEMALE (J2.11), MINI_PCIE (J8.31)
PCIe.TX_P: HDConn_FEMALE (J2.9), MINI_PCIE (J8.33)
PDM.CK: HDConn_FEMALE (J1.66), CAMERA_CONNECTOR (J4.16)
PDM.D0: HDConn_FEMALE (J1.68), CAMERA_CONNECTOR (J4.17)
PWM.6: TOP (J5.33), POWER (R69.1), HDConn_FEMALE (J2.62)
PWM.7: TOP (J5.35), FIELDBUS (R51.1), HDConn_FEMALE (J2.64)
PWM.8: TOP (J5.37), FIELDBUS (R44.1), HDConn_FEMALE (J2.66)
PWM.9: TOP (J5.39), HDConn_FEMALE (J2.68), MINI_PCIE (R63.1)
SAI.CK: TOP (J5.15), HDConn_FEMALE (J2.49)
SAI.D0: TOP (J5.19), HDConn_FEMALE (J2.53)
SAI.D1: TOP (J5.21), HDConn_FEMALE (J2.55)
SAI.FS: TOP (J5.17), HDConn_FEMALE (J2.51)
SDC.CD: HDConn_FEMALE (J1.67), SD_CONNECTOR (J11.CD1 SDC_CD.X)
SDC.CLK: HDConn_FEMALE (J1.55), SD_CONNECTOR (J11.5 SDC_CLK.X)
SDC.CMD: HDConn_FEMALE (J1.57), SD_CONNECTOR (J11.3 SDC_CMD.X)
SDC.D0: HDConn_FEMALE (J1.59), SD_CONNECTOR (J11.7 SDC_D0.X)
SDC.D1: HDConn_FEMALE (J1.61), SD_CONNECTOR (J11.8 SDC_D1.X)
SDC.D2: HDConn_FEMALE (J1.63), SD_CONNECTOR (J11.1 SDC_D2.X)
SDC.D3: HDConn_FEMALE (J1.65), SD_CONNECTOR (J11.2 SDC_D3.X)
SERIAL0.CTS: TOP (SERIAL0_CTS.X), FIELDBUS (U4.6), HDConn_FEMALE (J1.40)
SERIAL0.RTS: TOP (SERIAL0_RTS.X), FIELDBUS (U4.21), HDConn_FEMALE (J1.38)
SERIAL0.RX: TOP (SERIAL0_RX.X), FIELDBUS (U4.7), HDConn_FEMALE (J1.36), DEBUGGER (U16.3)
SERIAL0.TX: TOP (SERIAL0_TX.X), FIELDBUS (U4.22), HDConn_FEMALE (J1.34), DEBUGGER (U19.3)
SERIAL1.CTS: TOP (SERIAL1_CTS.X), HDConn_FEMALE (J1.39), CELL_MODEM (U20.3)
SERIAL1.RTS: TOP (SERIAL1_RTS.X), HDConn_FEMALE (J1.37), CELL_MODEM (U22.3)
SERIAL1.RX: TOP (SERIAL1_RX.X), HDConn_FEMALE (J1.35), CELL_MODEM (U8.3), DEBUGGER (U16.1)
SERIAL1.TX: TOP (SERIAL1_TX.X), HDConn_FEMALE (J1.33), CELL_MODEM (U21.3), DEBUGGER (U19.1)
SERIAL2.RX: TOP (SERIAL2_RX.X), HDConn_FEMALE (J2.28), DEBUGGER (U15.42)
SERIAL2.TX: TOP (SERIAL2_TX.X), HDConn_FEMALE (J2.26), DEBUGGER (U15.43)
SERIAL3.CTS: TOP (J5.30), HDConn_FEMALE (J2.31)
SERIAL3.RTS: TOP (J5.28), HDConn_FEMALE (J2.29)
SERIAL3.RX: TOP (J5.26 SERIAL3_RX.X), HDConn_FEMALE (J2.27), LORA (U23.24), DEBUGGER (U18.3)
SERIAL3.TX: TOP (J5.24 SERIAL3_TX.X), HDConn_FEMALE (J2.25), LORA (U23.23), DEBUGGER (U17.3)
SPDIF.RX: TOP (J5.25), HDConn_FEMALE (J1.76)
SPDIF.TX: TOP (J5.23), HDConn_FEMALE (J1.74)
SPI1.CK: TOP (J5.18), HDConn_FEMALE (J2.38)
SPI1.CS: TOP (J5.16), HDConn_FEMALE (J2.36)
SPI1.MISO: TOP (J5.20), HDConn_FEMALE (J2.40)
SPI1.MOSI: TOP (J5.22), HDConn_FEMALE (J2.42)
~{USB_EN0}: USB_HUB (HUB_EN0.X Q5.6 R41.1 R114.2), USBA_CONNECTORS (U7.4)
~{USB_EN1}: USB_HUB (HUB_EN1.X Q5.3 R42.1 R115.2), USBA_CONNECTORS (U7.5)
USB_EN2: CELL_MODEM (R20.2), USB_HUB (HUB_EN2.X Q6.3 R56.2)
USB_FS.D_N: TOP (USB_FS_DN.X), HDConn_FEMALE (J1.28), USB_HUB (U3.30)
USB_FS.D_P: TOP (USB_FS_DP.X), HDConn_FEMALE (J1.26), USB_HUB (U3.31)
USB_FS.ID: TOP (USB_FS_ID.X), HDConn_FEMALE (J1.30)
USB_FS.VBUS: TOP (USB_FS_VBUS.X), HDConn_FEMALE (J1.24)
USB_H0.D_N: TOP (USB_H0_DN.X), USB_HUB (R102.1), USBA_CONNECTORS (D5.3 J15.2)
USB_H0.D_P: TOP (USB_H0_DP.X), USB_HUB (R99.1), USBA_CONNECTORS (D5.2 J15.3)
USB_H1.D_N: TOP (USB_H1_DN.X), USB_HUB (R104.1), USBA_CONNECTORS (D6.3 J15.6)
USB_H1.D_P: TOP (USB_H1_DP.X), USB_HUB (R103.1), USBA_CONNECTORS (D6.2 J15.7)
USB_H2.D_N: TOP (USB_H2_DN.X), CELL_MODEM (R5.2), USB_HUB (R31.1)
USB_H2.D_P: TOP (USB_H2_DP.X), CELL_MODEM (R4.2), USB_HUB (R30.1)
USB_H3.D_N: TOP (USB_H3_DN.X), MINI_PCIE (J8.36), USB_HUB (R108.1)
USB_H3.D_P: TOP (USB_H3_DP.X), MINI_PCIE (J8.38), USB_HUB (R107.1)
USB_OC0: USB_HUB (U3.13), USBA_CONNECTORS (U7.10)
USB_OC1: USB_HUB (U3.17), USBA_CONNECTORS (U7.6)
VIN: TOP (R92.2), HDConn_FEMALE (J1.21 J1.32 J1.41 J1.48)

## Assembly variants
Complete: not fitted C16 C17 C21 C81 C158 CN2 CN3 D8 H1 H2 H3 H4 J19 R43 R60 R61 R85 R86 R87 R92 R93 R94 R113 R114 R115 R119
NoLora_NoAudio: not fitted C11 C12 C13 C14 C15 C16 C17 C19 C21 C22 C23 C24 C25 C26 C27 C28 C31 C32 C33 C35 C36 C37 C38 C39 C40 C41 C42 C43 C44 C45 C46 C47 C48 C49 C50 C51 C60 C63 C81 C96 C97 C98 C99 C100 C101 C102 C103 C105 C107 C108 C109 C110 C111 C112 C113 C114 C115 C117 C157 C158 CN1 CN2 CN3 D7 D8 D11 D12 H1 H2 H3 H4 J9 J10 J12 J13 J14 J19 J20 PB2 Q4 R9 R10 R11 R12 R13 R14 R15 R16 R18 R19 R21 R22 R23 R24 R25 R26 R27 R28 R29 R32 R33 R34 R35 R36 R37 R38 R39 R40 R43 R57 R60 R61 R62 R79 R79 R80 R81 R82 R83 R84 R85 R86 R87 R89 R90 R91 R92 R93 R94 R97 R98 R100 R101 R105 R106 R109 R110 R113 R114 R115 R119 U2 U9 U10 U10 U14 U15 U16 U17 U18 U19 U23 Y3
NoModem_NoAudio: not fitted C1 C2 C3 C4 C5 C6 C7 C8 C9 C10 C16 C17 C19 C21 C22 C23 C24 C25 C26 C27 C28 C29 C30 C31 C32 C33 C35 C36 C37 C38 C39 C40 C41 C42 C43 C44 C45 C46 C47 C48 C49 C50 C51 C63 C81 C96 C97 C98 C99 C100 C101 C102 C103 C105 C107 C108 C109 C110 C111 C112 C113 C114 C115 C117 C134 C135 C136 C137 C138 C139 C141 C142 C143 C157 C158 CN1 CN2 CN3 D1 D2 D3 D4 D7 D8 D9 D11 D12 H1 H2 H3 H4 J3 J10 J12 J13 J14 J19 J20 L1 L2 PB2 Q1 Q4 Q7 R1 R2 R3 R4 R5 R6 R7 R8 R17 R20 R21 R22 R23 R24 R25 R26 R27 R28 R29 R32 R33 R34 R35 R36 R37 R38 R39 R40 R43 R57 R60 R61 R62 R79 R79 R80 R81 R82 R83 R84 R85 R86 R87 R89 R90 R91 R92 R93 R94 R97 R98 R100 R101 R105 R106 R109 R110 R113 R114 R115 R119 SIM1 U1 U2 U7 U8 U9 U10 U10 U14 U15 U16 U17 U18 U19 U20 U21 U22 Y3
NoLora_NoModem_NoAudio: not fitted C1 C2 C3 C4 C5 C6 C7 C8 C9 C10 C11 C12 C13 C14 C15 C16 C17 C19 C21 C22 C23 C24 C25 C26 C27 C28 C29 C30 C31 C32 C33 C35 C36 C37 C38 C39 C40 C41 C42 C43 C44 C45 C46 C47 C48 C49 C50 C51 C60 C63 C81 C96 C97 C98 C99 C100 C101 C102 C103 C105 C107 C108 C109 C110 C111 C112 C113 C114 C115 C117 C134 C135 C136 C137 C138 C139 C141 C142 C143 C157 C158 CN1 CN2 CN3 D1 D2 D3 D4 D7 D8 D9 D11 D12 H1 H2 H3 H4 J3 J9 J10 J12 J13 J14 J19 J20 L1 L2 PB2 Q1 Q4 Q7 R1 R2 R3 R4 R5 R6 R7 R8 R9 R10 R11 R12 R13 R14 R15 R16 R17 R18 R19 R20 R21 R22 R23 R24 R25 R26 R27 R28 R29 R32 R33 R34 R35 R36 R37 R38 R39 R40 R43 R57 R60 R61 R62 R79 R79 R80 R81 R82 R83 R84 R85 R86 R87 R89 R90 R91 R92 R93 R94 R97 R98 R100 R101 R105 R106 R109 R110 R113 R114 R115 R119 SIM1 U1 U2 U7 U8 U9 U10 U10 U14 U15 U16 U17 U18 U19 U20 U21 U22 U23 Y3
